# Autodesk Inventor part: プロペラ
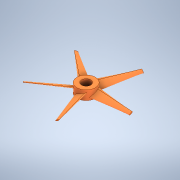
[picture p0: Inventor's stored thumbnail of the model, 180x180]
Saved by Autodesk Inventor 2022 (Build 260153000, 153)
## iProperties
Created: 2024-12
Part Number: プロペラ
Material: 一般
Document SubType Name: Modeling
Designer: jsat7
Density: 1 g/cm^3
Appearance: 既定
Author: jsat7
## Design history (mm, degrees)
sketch "スケッチ1"
  geometry: C1 r 3 at (0, 0); 1 further point
  constraints: 1 centre point, 1 coincident
  dimensions: "d0" = 6 diameter of C1
extrude "押し出し1" new body sketch "スケッチ1" distance "d1" = 3; taper "d2" = 0 deg
sketch "スケッチ2"
  geometry: 2 further points; 1 other entity
  constraints: 2 other
node "作業平面1"
sketch "スケッチ3"
  geometry: C1 r 5.183 at (1.551, 0); 1 further point
  constraints: 1 centre point
feature "ロフト1" sketch "スケッチ3" dims "d4" = 0, "d5" = 90 deg, "d6" = 0, "d7" = 90 deg
pattern_circular "円形状パターン1" dims angle "d9" = 360 deg
sketch "スケッチ4"
  geometry: C1 r 1.5 at (0, 0); 1 further point
  constraints: 1 centre point, 1 coincident
  dimensions: "d11" = 3 diameter of C1
extrude "押し出し2" cut sketch "スケッチ4" distance "d12" = 3; taper "d13" = 0 deg
node "ソリッド1"
other parameters: "d3" = 14.64
